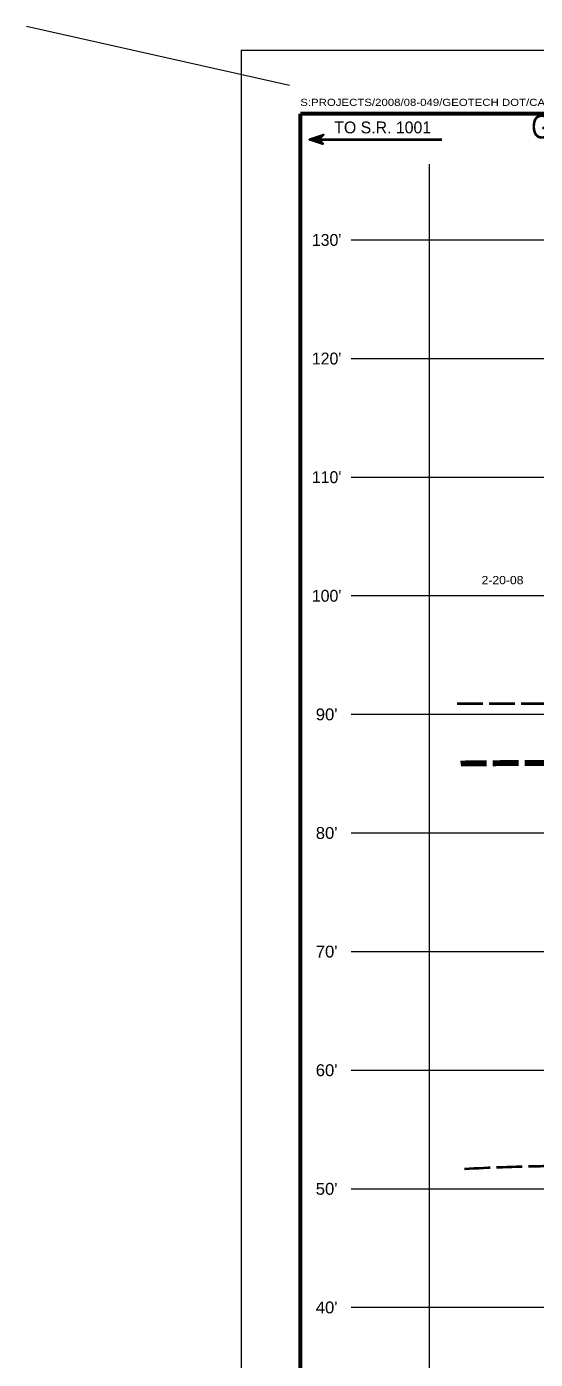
# Model space of a CAD drawing. Extents: x -76 to 974, y -1080 to -735.
# Drawn here: x 560.1 to 603, y -996.5 to -884.1 of the extents above; entities that cross this region are included whole.
import ezdxf
from ezdxf.enums import TextEntityAlignment as Align

# ---------------------------------------------------------------- set-up
doc = ezdxf.new("R2010")
doc.units = 0
doc.header["$LTSCALE"] = 0.36
doc.linetypes.add('LONG_DASHED', pattern=[7.5, 6, -1.5])
for name, color, linetype, lineweight in [('10', 7, 'Continuous', 35), ('27', 7, 'Continuous', 40), ('28', 7, 'LONG_DASHED', 60), ('63', 7, 'Continuous', 35), ('7', 7, 'Continuous', 13)]:
    doc.layers.add(name, color=color, linetype=linetype, lineweight=lineweight)

msp = doc.modelspace()

# ---------------------------------------------------------------- hatches: boundary and pattern name
at = {"layer": '10'}
msp.add_hatch(color=256, dxfattribs=at).paths.add_polyline_path([(585.1227, -894.0323), (583.9227, -893.6323), (585.1227, -893.2323), (584.7227, -893.6323)])

# ---------------------------------------------------------------- linework, layer by layer
msp.add_lwpolyline([(585.1227, -894.0323), (583.9227, -893.6323), (585.1227, -893.2323), (584.7227, -893.6323)], close=True, dxfattribs=at)
at = {"layer": '27', "lineweight": 13}
msp.add_line((582.2531, -889.0898), (560.0632, -884.1181), dxfattribs=at)
at = {"layer": '27'}
msp.add_line((583.9229, -893.6322), (595.0976, -893.6322), dxfattribs=at)
at = {"layer": '28', "lineweight": 40}
for points in [[(596.3883, -941.1907), (603.4063, -941.1789), (607.1737, -941.1789), (609.6738, -941.1789), (661.0289, -942.6789), (664.7963, -942.6789), (667.2963, -942.6789), (677.9134, -942.6789)], [(597.0178, -980.4083), (603.4063, -980.1789), (607.1738, -980.1789), (609.6738, -980.1789), (661.0289, -977.6789), (664.7963, -977.6789), (667.2963, -977.6789), (677.5986, -977.6789)]]:
    msp.add_spline(points, degree=3, dxfattribs=at)
at = {"layer": '28', "lineweight": 100}
msp.add_spline([(596.7031, -946.2307), (603.4063, -946.1789), (607.1738, -946.1789), (609.6738, -946.1789), (661.0289, -947.6789), (664.7963, -947.6789), (667.2963, -947.6789), (678.3855, -947.6789)], degree=3, dxfattribs=at)
at = {"layer": '63', "lineweight": 13}
for q in [(578.1701, -1056.1123), (688.1701, -886.1123)]:
    msp.add_line((578.1701, -886.1123), q, dxfattribs=at)
at = {"layer": '63', "lineweight": 60}
for p in [(583.1701, -1052.1123), (683.1701, -891.4595)]:
    msp.add_line(p, (583.1701, -891.4595), dxfattribs=at)
at = {"layer": '7'}
for p, q in [((594.0463, -1033.3123), (594.0463, -895.7205)), ((587.4376, -902.09), (678.7313, -902.09)), ((587.4376, -912.09), (678.7313, -912.09)), ((587.4376, -922.09), (678.7313, -922.09)), ((587.4376, -932.09), (607.1738, -932.09)), ((587.4376, -942.09), (607.1738, -942.09)), ((587.4376, -952.09), (607.1738, -952.09)), ((587.4376, -962.09), (607.1738, -962.09)), ((587.4376, -972.09), (607.1738, -972.09)), ((587.4376, -982.09), (607.1738, -982.09)), ((587.4376, -992.09), (664.7963, -992.09))]:
    msp.add_line(p, q, dxfattribs=at)

# ---------------------------------------------------------------- texts
at = {"layer": '27'}
msp.add_text('TO S.R. 1001', height=1, dxfattribs=at).set_placement((590.1069, -893.1141), align=Align.CENTER)
at = {"layer": '27', "width": 1.1}
msp.add_text('2-20-08', height=0.6976, dxfattribs=at).set_placement((600.2195, -931.1273), align=Align.CENTER)
at = {"layer": '63', "width": 1.2}
msp.add_text('S:PROJECTS/2008/08-049/GEOTECH DOT/CADD/R-2719A 198-199 PROFILE-XSEC.DGN', height=0.6, dxfattribs=at).set_placement((583.1537, -890.8007))
at = {"layer": '63'}
for s, height, width, p in [("GENERALIZED SUBSURFACE PROFILE 70' RIGHT OF -L-", 2, 0.85, (633.17, -893.5476)), ("90'", 1, 1.05, (585.3759, -942.6008)), ("80'", 1, 1.05, (585.3759, -952.6008)), ("70'", 1, 1.05, (585.3759, -962.6008)), ("60'", 1, 1.05, (585.3759, -972.6008)), ("50'", 1, 1.05, (585.3759, -982.6008)), ("40'", 1, 1.05, (585.3759, -992.6008))]:
    msp.add_text(s, height=height, dxfattribs=dict(at, width=width)).set_placement(p, align=Align.CENTER)
for s, p in [("130'", (585.3759, -902.6008)), ("120'", (585.3759, -912.6008)), ("110'", (585.376, -922.6008)), ("100'", (585.3759, -932.6008))]:
    msp.add_text(s, height=1, dxfattribs=at).set_placement(p, align=Align.CENTER)

doc.saveas('drawing.dxf')
